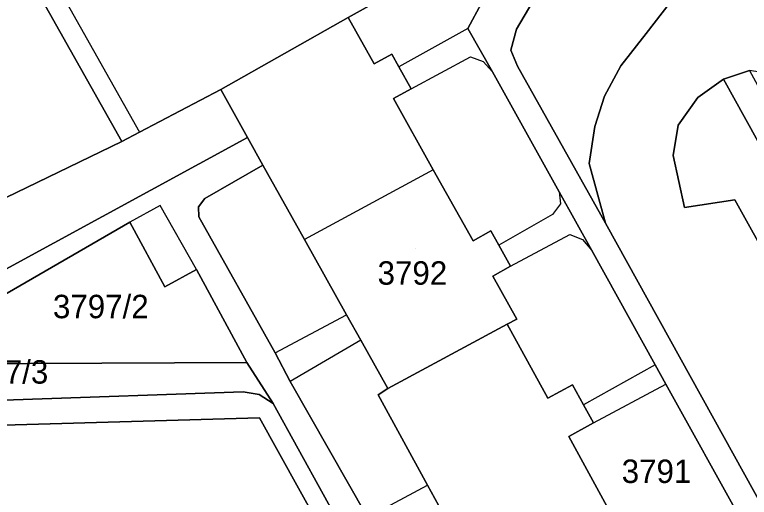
# Model space of a CAD drawing. Extents: x -262715 to -259381, y -1237238 to -1231182.
# Drawn here: x -261574 to -261511.3, y -1235520.8 to -1235479.6 of the extents above; entities that cross this region are included whole.
import ezdxf

# ---------------------------------------------------------------- set-up
doc = ezdxf.new("R2010")
doc.units = 0
for name, color, linetype in [('body_kn', 7, 'Continuous'), ('kladpar_druhypozemkov', 7, 'Continuous'), ('kladpar_hranice', 7, 'Continuous'), ('kladpar_parcelnecisla', 7, 'Continuous'), ('kladpar_plochy', 7, 'Continuous'), ('zappar_hrandruhpozemk', 7, 'Continuous')]:
    doc.layers.add(name, color=color, linetype=linetype)

msp = doc.modelspace()

# ---------------------------------------------------------------- linework, layer by layer
at = {"layer": 'body_kn'}
for p, q in [((-261545.55, -1235479.87), (-261545.55, -1235479.87)), ((-261545.55, -1235479.87), (-261545.55, -1235479.87)), ((-261535.33, -1235480.81), (-261535.33, -1235480.81)), ((-261535.33, -1235480.81), (-261535.33, -1235480.81)), ((-261531.17, -1235480.86), (-261531.17, -1235480.86)), ((-261520.11, -1235481.22), (-261520.11, -1235481.22)), ((-261541.83, -1235482.98), (-261541.83, -1235482.98)), ((-261535.1, -1235483.22), (-261535.1, -1235483.22)), ((-261531.67, -1235482.64), (-261531.67, -1235482.64)), ((-261543.33, -1235483.82), (-261543.33, -1235483.82)), ((-261534.02, -1235483.6), (-261534.02, -1235483.6)), ((-261541.22, -1235484.07), (-261541.22, -1235484.07)), ((-261533.21, -1235484.5), (-261533.21, -1235484.5)), ((-261531.08, -1235484), (-261531.08, -1235484)), ((-261522.27, -1235483.97), (-261522.27, -1235483.97)), ((-261513.48, -1235485.13), (-261513.48, -1235485.13)), ((-261513.48, -1235485.13), (-261513.48, -1235485.13)), ((-261556.44, -1235486), (-261556.44, -1235486)), ((-261540.17, -1235485.94), (-261540.17, -1235485.94)), ((-261540.17, -1235485.94), (-261540.17, -1235485.94)), ((-261541.67, -1235486.78), (-261541.67, -1235486.78)), ((-261523.67, -1235486.57), (-261523.67, -1235486.57)), ((-261515.69, -1235486.68), (-261515.69, -1235486.68)), ((-261524.49, -1235489.16), (-261524.49, -1235489.16)), ((-261517.37, -1235489.05), (-261517.37, -1235489.05)), ((-261563.37, -1235489.64), (-261563.37, -1235489.64)), ((-261554.15, -1235490.1), (-261554.15, -1235490.1)), ((-261564.9, -1235490.45), (-261564.9, -1235490.45)), ((-261517.78, -1235491.64), (-261517.78, -1235491.64)), ((-261552.83, -1235492.46), (-261552.83, -1235492.46)), ((-261524.98, -1235492.33), (-261524.98, -1235492.33)), ((-261538.28, -1235492.85), (-261538.28, -1235492.85)), ((-261538.28, -1235492.85), (-261538.28, -1235492.85)), ((-261527.53, -1235494.72), (-261527.53, -1235494.72)), ((-261527.53, -1235494.72), (-261527.53, -1235494.72)), ((-261557.81, -1235495.29), (-261557.81, -1235495.29)), ((-261527.41, -1235495.77), (-261527.41, -1235495.77)), ((-261512.53, -1235495.42), (-261512.53, -1235495.42)), ((-261561.61, -1235495.91), (-261561.61, -1235495.91)), ((-261558.34, -1235496.01), (-261558.34, -1235496.01)), ((-261516.83, -1235496.06), (-261516.83, -1235496.06)), ((-261558.32, -1235496.87), (-261558.32, -1235496.87)), ((-261528.09, -1235496.68), (-261528.09, -1235496.68)), ((-261564.19, -1235497.32), (-261564.19, -1235497.32)), ((-261523.57, -1235497.42), (-261523.57, -1235497.42)), ((-261533.36, -1235498.07), (-261533.36, -1235498.07)), ((-261549.28, -1235498.79), (-261549.28, -1235498.79)), ((-261534.88, -1235498.92), (-261534.88, -1235498.92)), ((-261526.61, -1235498.37), (-261526.61, -1235498.37)), ((-261525.53, -1235498.8), (-261525.53, -1235498.8)), ((-261532.68, -1235499.28), (-261532.68, -1235499.28)), ((-261524.73, -1235499.75), (-261524.73, -1235499.75)), ((-261558.51, -1235501.37), (-261558.51, -1235501.37)), ((-261558.51, -1235501.37), (-261558.51, -1235501.37)), ((-261531.68, -1235501.07), (-261531.68, -1235501.07)), ((-261531.68, -1235501.07), (-261531.68, -1235501.07)), ((-261533.2, -1235501.92), (-261533.2, -1235501.92)), ((-261561.21, -1235502.83), (-261561.21, -1235502.83)), ((-261545.69, -1235505.22), (-261545.69, -1235505.22)), ((-261531.14, -1235505.59), (-261531.14, -1235505.59)), ((-261531.97, -1235506.03), (-261531.97, -1235506.03)), ((-261531.97, -1235506.03), (-261531.97, -1235506.03)), ((-261544.47, -1235507.4), (-261544.47, -1235507.4)), ((-261544.47, -1235507.4), (-261544.47, -1235507.4)), ((-261551.8, -1235508.47), (-261551.8, -1235508.47)), ((-261551.8, -1235508.47), (-261551.8, -1235508.47)), ((-261554.22, -1235509.29), (-261554.22, -1235509.29)), ((-261554.22, -1235509.29), (-261554.22, -1235509.29)), ((-261519.32, -1235509.5), (-261519.32, -1235509.5)), ((-261519.32, -1235509.5), (-261519.32, -1235509.5)), ((-261550.51, -1235510.92), (-261550.51, -1235510.92)), ((-261526.39, -1235511.2), (-261526.39, -1235511.2)), ((-261518.43, -1235511.15), (-261518.43, -1235511.15)), ((-261554.52, -1235511.81), (-261554.52, -1235511.81)), ((-261553.17, -1235512.03), (-261553.17, -1235512.03)), ((-261543, -1235512.07), (-261543, -1235512.07)), ((-261542.16, -1235511.53), (-261542.16, -1235511.53)), ((-261528.5, -1235512.35), (-261528.5, -1235512.35)), ((-261551.97, -1235512.81), (-261551.97, -1235512.81)), ((-261551.97, -1235512.81), (-261551.97, -1235512.81)), ((-261525.45, -1235512.92), (-261525.45, -1235512.92)), ((-261553.12, -1235514.02), (-261553.12, -1235514.02)), ((-261553.12, -1235514.02), (-261553.12, -1235514.02)), ((-261524.6, -1235514.46), (-261524.6, -1235514.46)), ((-261524.6, -1235514.46), (-261524.6, -1235514.46)), ((-261526.71, -1235515.61), (-261526.71, -1235515.61)), ((-261538.78, -1235519.77), (-261538.78, -1235519.77))]:
    msp.add_line(p, q, dxfattribs=at)
at = {"layer": 'kladpar_druhypozemkov'}
for p, q in [((-261539.79, -1235499.53), (-261539.79, -1235499.53)), ((-261566.08, -1235503.29), (-261566.08, -1235503.29)), ((-261519.15, -1235517.76), (-261519.15, -1235517.76))]:
    msp.add_line(p, q, dxfattribs=at)
at = {"layer": 'kladpar_hranice'}
for points in [[(-261549.95, -1235428.05), (-261540.84, -1235441.31), (-261537.2, -1235440.72), (-261534.21, -1235445.87), (-261536.49, -1235448.93), (-261525.23, -1235468.52), (-261530.91, -1235471.69), (-261551.91, -1235433.86), (-261584.55, -1235451.99), (-261586.1, -1235452.86), (-261564.9, -1235490.45), (-261578.43, -1235496.98), (-261599.2, -1235458.61), (-261600.58, -1235454.79), (-261589.82, -1235449.08), (-261585.7, -1235447.27), (-261583.96, -1235446.24), (-261569.98, -1235438.57), (-261567.38, -1235437.21), (-261549.95, -1235428.05)], [(-261551.91, -1235433.86), (-261530.91, -1235471.69), (-261545.55, -1235479.87), (-261556.44, -1235486), (-261563.37, -1235489.64), (-261564.9, -1235490.45), (-261586.1, -1235452.86), (-261584.55, -1235451.99), (-261551.91, -1235433.86)], [(-261606.13, -1235462.18), (-261599.2, -1235458.61), (-261578.43, -1235496.98), (-261564.9, -1235490.45), (-261563.37, -1235489.64), (-261556.44, -1235486), (-261554.15, -1235490.1), (-261591.64, -1235510.5), (-261613.2, -1235510.23), (-261616.54, -1235508.19), (-261623.33, -1235508.1), (-261624.56, -1235508.73), (-261624.29, -1235486.05), (-261613.28, -1235486.09)], [(-261467.86, -1235597.89), (-261523.57, -1235497.42), (-261524.98, -1235492.33), (-261524.49, -1235489.16), (-261523.67, -1235486.57), (-261522.27, -1235483.97), (-261520.11, -1235481.22), (-261516.47, -1235476.53), (-261515.41, -1235473.33), (-261514.71, -1235472.57), (-261514.71, -1235470.58), (-261516.2, -1235464.94), (-261503.65, -1235487.68), (-261504.9, -1235486.07), (-261506.32, -1235485.18), (-261511.26, -1235484.38), (-261513.48, -1235485.13), (-261515.69, -1235486.68), (-261517.37, -1235489.05), (-261517.78, -1235491.64), (-261516.83, -1235496.06), (-261512.53, -1235495.42), (-261492.77, -1235530.91)], [(-261530.91, -1235471.69), (-261525.23, -1235468.52), (-261523.85, -1235470.91), (-261523.67, -1235473.55), (-261525.79, -1235473.1), (-261526.9, -1235473.61), (-261531.17, -1235480.86), (-261531.67, -1235482.64), (-261531.08, -1235484), (-261523.57, -1235497.42), (-261467.86, -1235597.89)], [(-261523.45, -1235521.56), (-261526.71, -1235515.61), (-261524.6, -1235514.46), (-261525.45, -1235512.92), (-261526.39, -1235511.2), (-261528.5, -1235512.35), (-261531.97, -1235506.03), (-261531.14, -1235505.59), (-261533.2, -1235501.92), (-261531.68, -1235501.07), (-261532.68, -1235499.28), (-261533.36, -1235498.07), (-261534.88, -1235498.92), (-261538.28, -1235492.85), (-261541.67, -1235486.78), (-261540.17, -1235485.94), (-261541.22, -1235484.07), (-261541.83, -1235482.98), (-261543.33, -1235483.82), (-261545.55, -1235479.87), (-261530.91, -1235471.69)], [(-261511.85, -1235522.97), (-261518.43, -1235511.15), (-261519.32, -1235509.5), (-261524.73, -1235499.75), (-261527.53, -1235494.72), (-261533.21, -1235484.5), (-261535.33, -1235480.81), (-261530.66, -1235472.13), (-261530.91, -1235471.69)], [(-261530.91, -1235471.69), (-261530.66, -1235472.13), (-261535.33, -1235480.81), (-261533.21, -1235484.5), (-261527.53, -1235494.72), (-261524.73, -1235499.75), (-261519.32, -1235509.5), (-261518.43, -1235511.15), (-261511.85, -1235522.97)], [(-261518.12, -1235473.75), (-261516.47, -1235476.53), (-261520.11, -1235481.22), (-261522.27, -1235483.97), (-261523.67, -1235486.57), (-261524.49, -1235489.16), (-261524.98, -1235492.33), (-261523.57, -1235497.42), (-261531.08, -1235484), (-261531.67, -1235482.64), (-261531.17, -1235480.86), (-261526.9, -1235473.61), (-261525.79, -1235473.1), (-261523.67, -1235473.55), (-261521.35, -1235473.6), (-261518.12, -1235473.75)], [(-261545.55, -1235479.87), (-261543.33, -1235483.82), (-261541.83, -1235482.98), (-261541.22, -1235484.07), (-261540.17, -1235485.94), (-261541.67, -1235486.78), (-261538.28, -1235492.85), (-261534.88, -1235498.92), (-261533.36, -1235498.07), (-261532.68, -1235499.28), (-261531.68, -1235501.07), (-261533.2, -1235501.92), (-261531.14, -1235505.59), (-261531.97, -1235506.03), (-261542.16, -1235511.53), (-261544.47, -1235507.4), (-261545.69, -1235505.22), (-261549.28, -1235498.79), (-261552.83, -1235492.46), (-261554.15, -1235490.1), (-261556.44, -1235486), (-261545.55, -1235479.87)], [(-261511.26, -1235484.38), (-261505.16, -1235495.58), (-261486.46, -1235529.8), (-261464.77, -1235569.24), (-261451.76, -1235592.59), (-261448.98, -1235591.27), (-261446.22, -1235598.57), (-261435.51, -1235617.79), (-261437.2, -1235618.84), (-261425.7, -1235639.75), (-261429.77, -1235642.57), (-261433.26, -1235646.14), (-261434.67, -1235644.77), (-261431.37, -1235641.24), (-261428.33, -1235639.13), (-261438.98, -1235619.69), (-261449.59, -1235600.46), (-261453.44, -1235593.54), (-261466.58, -1235569.82), (-261487.34, -1235532.32), (-261487.97, -1235531.18), (-261489.3, -1235528.78), (-261513.48, -1235485.13), (-261511.26, -1235484.38)], [(-261513.48, -1235485.13), (-261489.3, -1235528.78), (-261491.26, -1235530.07), (-261492.77, -1235530.91), (-261512.53, -1235495.42), (-261516.83, -1235496.06), (-261517.78, -1235491.64), (-261517.37, -1235489.05), (-261515.69, -1235486.68), (-261513.48, -1235485.13)], [(-261591.64, -1235510.5), (-261554.15, -1235490.1), (-261552.83, -1235492.46), (-261557.81, -1235495.29), (-261558.34, -1235496.01), (-261558.32, -1235496.87), (-261551.8, -1235508.47), (-261550.51, -1235510.92), (-261543.91, -1235522.5)], [(-261543.91, -1235522.5), (-261550.51, -1235510.92), (-261551.8, -1235508.47), (-261558.32, -1235496.87), (-261558.34, -1235496.01), (-261557.81, -1235495.29), (-261552.83, -1235492.46), (-261549.28, -1235498.79), (-261545.69, -1235505.22), (-261544.47, -1235507.4), (-261542.16, -1235511.53), (-261543, -1235512.07), (-261538.78, -1235519.77), (-261537.53, -1235522.05)], [(-261558.51, -1235501.37), (-261554.22, -1235509.29), (-261585.2, -1235509.43), (-261564.19, -1235497.32), (-261561.21, -1235502.83), (-261558.51, -1235501.37)], [(-261511.39, -1235586.29), (-261551.97, -1235512.81), (-261554.22, -1235509.29), (-261558.51, -1235501.37), (-261561.21, -1235502.83), (-261564.19, -1235497.32), (-261585.2, -1235509.43)], [(-261537.53, -1235522.05), (-261538.78, -1235519.77), (-261543, -1235512.07), (-261542.16, -1235511.53), (-261531.97, -1235506.03)], [(-261531.97, -1235506.03), (-261528.5, -1235512.35), (-261526.39, -1235511.2), (-261525.45, -1235512.92), (-261524.6, -1235514.46), (-261526.71, -1235515.61), (-261523.45, -1235521.56)], [(-261554.22, -1235509.29), (-261551.97, -1235512.81), (-261553.17, -1235512.03), (-261554.52, -1235511.81), (-261593.78, -1235513.16), (-261585.2, -1235509.43), (-261554.22, -1235509.29)], [(-261551.97, -1235512.81), (-261511.39, -1235586.29), (-261512.73, -1235586.81), (-261553.12, -1235514.02), (-261594.9, -1235515.2), (-261595.41, -1235514.45), (-261594.77, -1235513.5), (-261593.78, -1235513.16), (-261554.52, -1235511.81), (-261553.17, -1235512.03), (-261551.97, -1235512.81)], [(-261553.12, -1235514.02), (-261512.73, -1235586.81), (-261515.02, -1235588.3), (-261518.98, -1235590.57), (-261522.62, -1235592.63), (-261540.84, -1235603.28), (-261555.56, -1235612.17), (-261565.02, -1235606.46), (-261569.04, -1235604.04), (-261571.26, -1235602.7), (-261596.64, -1235556.57)], [(-261596.64, -1235556.57), (-261596.4, -1235550.86), (-261595.94, -1235541.17), (-261594.9, -1235515.2), (-261553.12, -1235514.02)]]:
    msp.add_lwpolyline(points, dxfattribs=at)
at = {"layer": 'kladpar_plochy'}
for p, q in [((-261594.9, -1235515.2), (-261553.12, -1235514.02)), ((-261553.12, -1235514.02), (-261512.73, -1235586.81))]:
    msp.add_line(p, q, dxfattribs=at)
for points in [[(-261549.95, -1235428.05), (-261540.84, -1235441.31), (-261537.2, -1235440.72), (-261534.21, -1235445.87), (-261536.49, -1235448.93), (-261525.23, -1235468.52), (-261530.91, -1235471.69), (-261551.91, -1235433.86), (-261584.55, -1235451.99), (-261586.1, -1235452.86), (-261564.9, -1235490.45), (-261578.43, -1235496.98), (-261599.2, -1235458.61), (-261600.58, -1235454.79), (-261589.82, -1235449.08), (-261585.7, -1235447.27), (-261583.96, -1235446.24), (-261569.98, -1235438.57), (-261567.38, -1235437.21)], [(-261551.91, -1235433.86), (-261530.91, -1235471.69), (-261545.55, -1235479.87), (-261556.44, -1235486), (-261563.37, -1235489.64), (-261564.9, -1235490.45), (-261586.1, -1235452.86), (-261584.55, -1235451.99)], [(-261518.12, -1235473.75), (-261516.47, -1235476.53), (-261520.11, -1235481.22), (-261522.27, -1235483.97), (-261523.67, -1235486.57), (-261524.49, -1235489.16), (-261524.98, -1235492.33), (-261523.57, -1235497.42), (-261531.08, -1235484), (-261531.67, -1235482.64), (-261531.17, -1235480.86), (-261526.9, -1235473.61), (-261525.79, -1235473.1), (-261523.67, -1235473.55), (-261521.35, -1235473.6)], [(-261545.55, -1235479.87), (-261543.33, -1235483.82), (-261541.83, -1235482.98), (-261541.22, -1235484.07), (-261540.17, -1235485.94), (-261541.67, -1235486.78), (-261538.28, -1235492.85), (-261534.88, -1235498.92), (-261533.36, -1235498.07), (-261532.68, -1235499.28), (-261531.68, -1235501.07), (-261533.2, -1235501.92), (-261531.14, -1235505.59), (-261531.97, -1235506.03), (-261542.16, -1235511.53), (-261544.47, -1235507.4), (-261545.69, -1235505.22), (-261549.28, -1235498.79), (-261552.83, -1235492.46), (-261554.15, -1235490.1), (-261556.44, -1235486)], [(-261511.26, -1235484.38), (-261505.16, -1235495.58), (-261486.46, -1235529.8), (-261464.77, -1235569.24), (-261451.76, -1235592.59), (-261448.98, -1235591.27), (-261446.22, -1235598.57), (-261435.51, -1235617.79), (-261437.2, -1235618.84), (-261425.7, -1235639.75), (-261429.77, -1235642.57), (-261433.26, -1235646.14), (-261434.67, -1235644.77), (-261431.37, -1235641.24), (-261428.33, -1235639.13), (-261438.98, -1235619.69), (-261449.59, -1235600.46), (-261453.44, -1235593.54), (-261466.58, -1235569.82), (-261487.34, -1235532.32), (-261487.97, -1235531.18), (-261489.3, -1235528.78), (-261513.48, -1235485.13)], [(-261513.48, -1235485.13), (-261489.3, -1235528.78), (-261491.26, -1235530.07), (-261492.77, -1235530.91), (-261512.53, -1235495.42), (-261516.83, -1235496.06), (-261517.78, -1235491.64), (-261517.37, -1235489.05), (-261515.69, -1235486.68)], [(-261558.51, -1235501.37), (-261554.22, -1235509.29), (-261585.2, -1235509.43), (-261564.19, -1235497.32), (-261561.21, -1235502.83)], [(-261554.22, -1235509.29), (-261551.97, -1235512.81), (-261553.17, -1235512.03), (-261554.52, -1235511.81), (-261593.78, -1235513.16), (-261585.2, -1235509.43)], [(-261551.97, -1235512.81), (-261511.39, -1235586.29), (-261512.73, -1235586.81), (-261553.12, -1235514.02), (-261594.9, -1235515.2), (-261595.41, -1235514.45), (-261594.77, -1235513.5), (-261593.78, -1235513.16), (-261554.52, -1235511.81), (-261553.17, -1235512.03)]]:
    msp.add_lwpolyline(points, close=True, dxfattribs=at)
for points in [[(-261467.86, -1235597.89), (-261523.57, -1235497.42), (-261524.98, -1235492.33), (-261524.49, -1235489.16), (-261523.67, -1235486.57), (-261522.27, -1235483.97), (-261520.11, -1235481.22), (-261516.47, -1235476.53), (-261515.41, -1235473.33), (-261514.71, -1235472.57), (-261514.71, -1235470.58), (-261516.2, -1235464.94), (-261503.65, -1235487.68), (-261504.9, -1235486.07), (-261506.32, -1235485.18), (-261511.26, -1235484.38), (-261513.48, -1235485.13), (-261515.69, -1235486.68), (-261517.37, -1235489.05), (-261517.78, -1235491.64), (-261516.83, -1235496.06), (-261512.53, -1235495.42), (-261492.77, -1235530.91)], [(-261511.85, -1235522.97), (-261518.43, -1235511.15), (-261519.32, -1235509.5), (-261524.73, -1235499.75), (-261527.53, -1235494.72), (-261533.21, -1235484.5), (-261535.33, -1235480.81), (-261530.66, -1235472.13), (-261530.91, -1235471.69), (-261525.23, -1235468.52), (-261523.85, -1235470.91), (-261523.67, -1235473.55), (-261525.79, -1235473.1), (-261526.9, -1235473.61), (-261531.17, -1235480.86), (-261531.67, -1235482.64), (-261531.08, -1235484), (-261523.57, -1235497.42), (-261467.86, -1235597.89)], [(-261523.45, -1235521.56), (-261526.71, -1235515.61), (-261524.6, -1235514.46), (-261525.45, -1235512.92), (-261526.39, -1235511.2), (-261528.5, -1235512.35), (-261531.97, -1235506.03), (-261531.14, -1235505.59), (-261533.2, -1235501.92), (-261531.68, -1235501.07), (-261532.68, -1235499.28), (-261533.36, -1235498.07), (-261534.88, -1235498.92), (-261538.28, -1235492.85), (-261541.67, -1235486.78), (-261540.17, -1235485.94), (-261541.22, -1235484.07), (-261541.83, -1235482.98), (-261543.33, -1235483.82), (-261545.55, -1235479.87), (-261530.91, -1235471.69)], [(-261530.66, -1235472.13), (-261535.33, -1235480.81), (-261533.21, -1235484.5), (-261527.53, -1235494.72), (-261524.73, -1235499.75), (-261519.32, -1235509.5), (-261518.43, -1235511.15), (-261511.85, -1235522.97)], [(-261578.43, -1235496.98), (-261564.9, -1235490.45), (-261563.37, -1235489.64), (-261556.44, -1235486), (-261554.15, -1235490.1), (-261591.64, -1235510.5)], [(-261591.64, -1235510.5), (-261554.15, -1235490.1), (-261552.83, -1235492.46), (-261557.81, -1235495.29), (-261558.34, -1235496.01), (-261558.32, -1235496.87), (-261551.8, -1235508.47), (-261550.51, -1235510.92), (-261543.91, -1235522.5)], [(-261543.91, -1235522.5), (-261550.51, -1235510.92), (-261551.8, -1235508.47), (-261558.32, -1235496.87), (-261558.34, -1235496.01), (-261557.81, -1235495.29), (-261552.83, -1235492.46), (-261549.28, -1235498.79), (-261545.69, -1235505.22), (-261544.47, -1235507.4), (-261542.16, -1235511.53), (-261543, -1235512.07), (-261538.78, -1235519.77), (-261537.53, -1235522.05)], [(-261511.39, -1235586.29), (-261551.97, -1235512.81), (-261554.22, -1235509.29), (-261558.51, -1235501.37), (-261561.21, -1235502.83), (-261564.19, -1235497.32), (-261585.2, -1235509.43)], [(-261537.53, -1235522.05), (-261538.78, -1235519.77), (-261543, -1235512.07), (-261542.16, -1235511.53), (-261531.97, -1235506.03), (-261528.5, -1235512.35), (-261526.39, -1235511.2), (-261525.45, -1235512.92), (-261524.6, -1235514.46), (-261526.71, -1235515.61), (-261523.45, -1235521.56)]]:
    msp.add_lwpolyline(points, dxfattribs=at)
at = {"layer": 'zappar_hrandruhpozemk'}
for p, q in [((-261584.55, -1235451.99), (-261563.37, -1235489.64)), ((-261535.33, -1235480.81), (-261541.22, -1235484.07)), ((-261540.17, -1235485.94), (-261535.1, -1235483.22)), ((-261538.28, -1235492.85), (-261549.28, -1235498.79)), ((-261561.61, -1235495.91), (-261564.19, -1235497.32)), ((-261558.51, -1235501.37), (-261561.61, -1235495.91)), ((-261528.09, -1235496.68), (-261532.68, -1235499.28)), ((-261531.68, -1235501.07), (-261526.61, -1235498.37)), ((-261551.8, -1235508.47), (-261545.69, -1235505.22)), ((-261544.47, -1235507.4), (-261550.51, -1235510.92)), ((-261519.32, -1235509.5), (-261525.45, -1235512.92)), ((-261524.6, -1235514.46), (-261518.43, -1235511.15)), ((-261543.91, -1235522.5), (-261538.78, -1235519.77))]:
    msp.add_line(p, q, dxfattribs=at)
for points in [[(-261535.1, -1235483.22), (-261534.02, -1235483.6), (-261533.21, -1235484.5)], [(-261527.53, -1235494.72), (-261527.41, -1235495.77), (-261528.09, -1235496.68)], [(-261526.61, -1235498.37), (-261525.53, -1235498.8), (-261524.73, -1235499.75)]]:
    msp.add_lwpolyline(points, dxfattribs=at)

# ---------------------------------------------------------------- texts
at = {"layer": 'kladpar_parcelnecisla'}
for s, p in [('3792', (-261543.042, -1235502.66)), ('3797/2', (-261570.774, -1235505.52)), ('3797/3', (-261579.35, -1235511.1)), ('3791', (-261522.186, -1235519.58))]:
    msp.add_text(s, height=2, dxfattribs=at).set_placement(p)

doc.saveas('drawing.dxf')
